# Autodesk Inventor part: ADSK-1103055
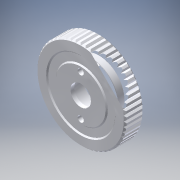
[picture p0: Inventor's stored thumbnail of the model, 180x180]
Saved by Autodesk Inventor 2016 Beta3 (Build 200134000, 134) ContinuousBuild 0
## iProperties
Shininess: 50.0
Length Units: 11272
Angle Units: 11279
Time Units: 11290
Mass Units: 11286
Length Display Precision: 4
Angle Display Precision: 2
Compacted: True
Created: 2000-08
Part Number: ADSK-1103055
Document SubType Name: Modeling
Mass: 8.22663 g
Surface Area: 26.2406 cm^2
Volume: 3.03566 cm^3
Density: 2.71 g/cm^3
Material: Aluminum-6061
Appearance: Aluminum - Flat
Density: 0.0
Volumn: 0.0
Area: 0.0
PropertySet Name: Model Information
Control State: 0
Master: False
Checked Out: False
Author: Autodesk, Inc.
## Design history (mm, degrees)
node "Extrusion1" dims "d1" = 6.35, "d2" = 0
  sketch "Sketch3"
    geometry: C1 r 15.24 at (-0.476, 0)
    constraints: 1 centre point
    dimensions: "d0" = 30.48 diameter of C1
node "Chamfer1" dims "d3" = 0.508, "d4" = 0.508, "d48" = 45 deg
node "Extrusion2" dims "d6" = 6.35, "d7" = 0
  sketch "Sketch4"
    geometry: L1 (0, 14.732)-(-0.508, 15.24); L2 (-0.508, 15.24)-(0.508, 15.24); L3 (0.508, 15.24)-(0, 14.732); C1 r 15.24 at (0, 0) reference; 1 further point
    constraints: 6 end point, 2 vertical alignment, 1 horizontal, 1 perpendicular, 1 tangent, 1 other
    dimensions: "d5" = 90 deg angle of L3 L1
node "Extrusion3" dims "d12" = 6.35, "d13" = -15 deg
  sketch "Sketch5"
    geometry: C1 r 5.715 at (0.476, 0); A1 r 14.732 centre (0.476, 0) between (3.813, 14.349) and (2.155, 14.636) reference
    constraints: 1 centre point, 1 coincident
    dimensions: "d11" = 11.43 diameter of C1
node "Extrusion4" dims "d15" = 6.35, "d16" = 0
  sketch "Sketch6"
    geometry: C1 r 4.014 at (-0.476, 0) reference; C2 r 4.128 at (-0.476, 0); A1 r 14.732 centre (-0.476, 0) between (10.089, 10.267) and (8.85, 11.405) reference
    constraints: 1 centre point, 1 coincident
    dimensions: "d14" = 8.255 diameter of C2
node "Hole1" dims "d18" = 2.0955, "d19" = 9.525, "d20" = 6.35, "d21" = 60 deg, "d22" = 19.05, "d23" = 118 deg
  sketch "Sketch7"
    geometry: 4 further points
    constraints: 1 vertical alignment, 1 other
    dimensions: "d17" = 6.985 distance of point (-0.476, 0) point (-0.476, 6.985)
node "Circular Pattern2" dims "d24" = 20, "d26" = 360 deg
workplane "Work Plane1"
  workaxis "Work Axis1"
  workaxis "Work Axis2"
node "Extrusion5" dims "d28" = 3.175, "d29" = -10 deg
  sketch "Sketch8"
    geometry: C1 r 1.048 at (0.476, -6.985) reference; C2 r 1.048 at (-5.573, -3.493) reference; C3 r 1.048 at (0.476, 6.985) reference; C4 r 8.668 at (0.476, 0); C5 r 13.462 at (0.476, 0); A1 r 14.732 centre (0.476, 0) between (-2.861, 14.349) and (-4.475, 13.875) reference; A2 r 14.732 centre (0.476, 0) between (3.813, 14.349) and (2.155, 14.636) reference
    constraints: 2 centre point, 2 coincident
    dimensions: "d27" = 1.27 radial gap between concentric circles of A1 C5; "d34" = 17.3355 diameter of C4
node "Fillet3" dims "d35" = 0.8128
node "Chamfer2" dims "d36" = 0.127, "d37" = 0.127, "d49" = 45 deg
node "Extrusion6" dims "d40" = 1.27, "d41" = 0
  sketch "Sketch9"
    geometry: C1 r 4.763 at (-0.476, 0); C2 r 3.493 at (-0.476, 0); A1 r 14.732 centre (-0.476, 0) between (2.861, 14.349) and (1.204, 14.636) reference
    constraints: 2 centre point, 2 coincident
    dimensions: "d38" = 6.985 diameter of C2; "d39" = 1.27 radial gap between concentric circles of C1 C2
node "Extrusion7" dims "d44" = 0.381, "d45" = 0
  sketch "Sketch10"
    geometry: C1 r 8.89 at (-0.476, 0); C2 r 11.43 at (-0.476, 0); C3 r 4.354 at (-0.476, 0) reference; A1 r 14.732 centre (-0.476, 0) between (5.259, -13.57) and (6.768, -12.828) reference
    constraints: 2 centre point, 2 concentric
    dimensions: "d42" = 17.78 diameter of C1; "d43" = 22.86 diameter of C2
node "Chamfer3" dims "d46" = 0.381, "d47" = 0.381, "d50" = 45 deg
body "Solid1"
node "Circular Pattern1" dims "d8" = 550, "d10" = 360 deg
